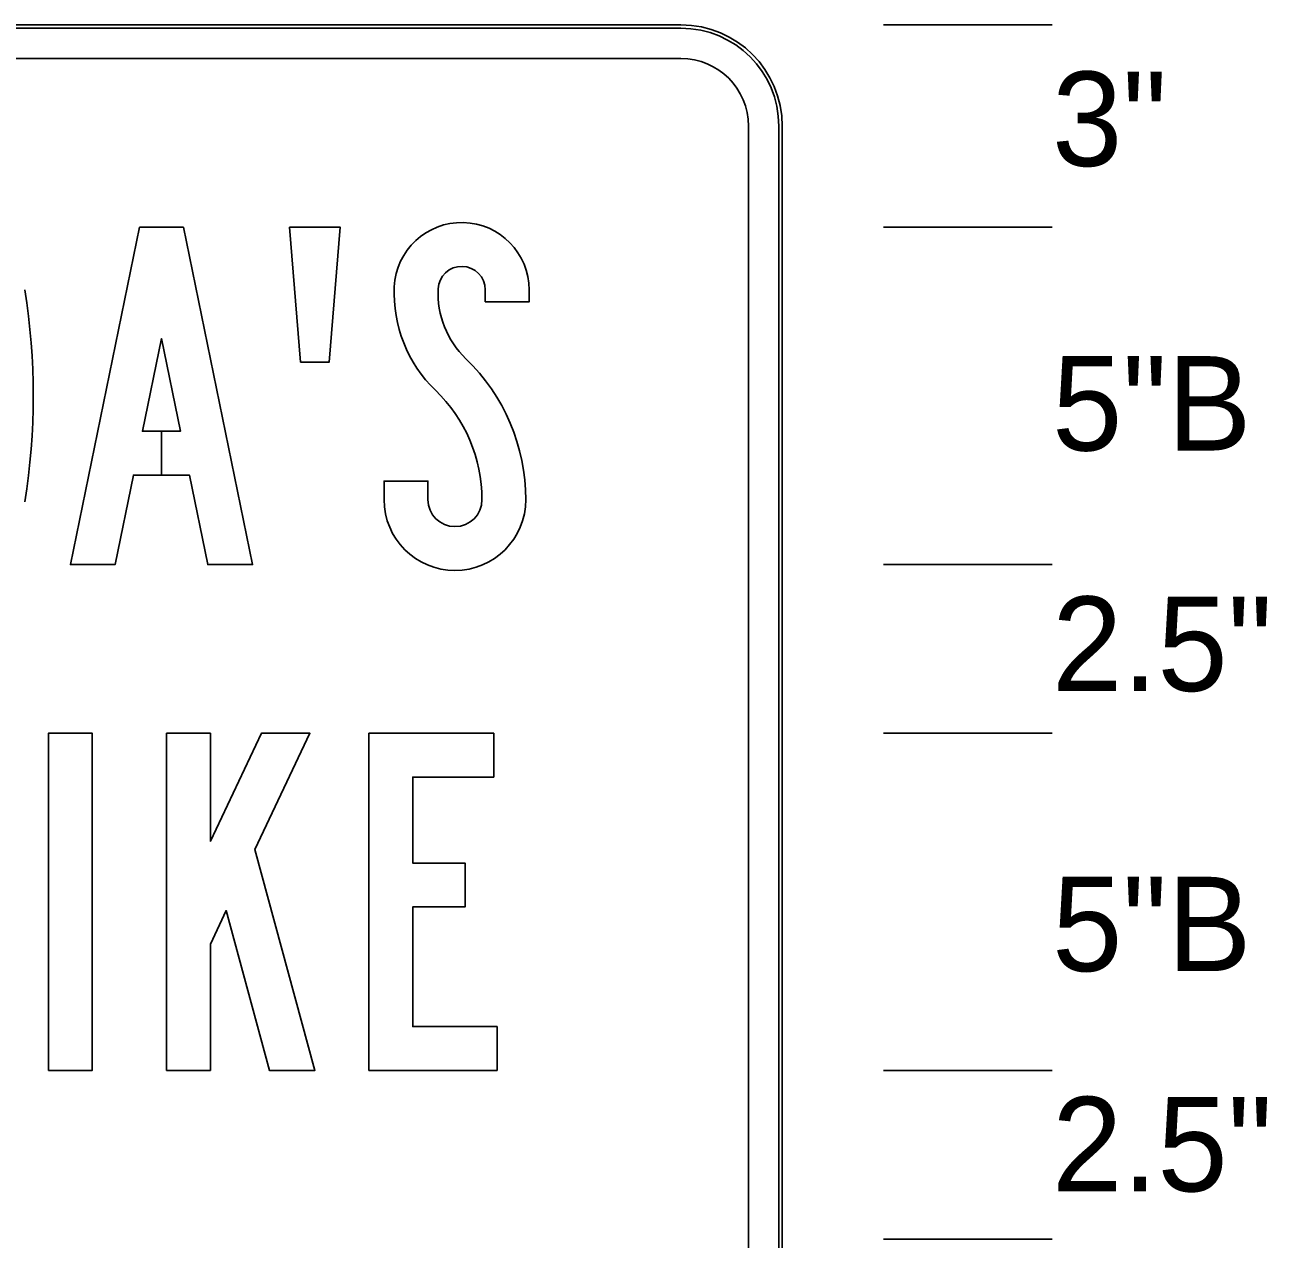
# Model space of a CAD drawing. Extents: x 0 to 770, y 0 to 495.
# Drawn here: x 157.86 to 203.89, y 97.62 to 142.62 of the extents above; entities that cross this region are included whole.
import ezdxf

# ---------------------------------------------------------------- set-up
doc = ezdxf.new("R2010")
doc.units = 0
for name, color, linetype in [('GSBWFill', 7, 'Continuous'), ('GSColorFill', 7, 'Continuous'), ('GSDims', 7, 'Continuous'), ('GSOutline', 7, 'Continuous')]:
    doc.layers.add(name, color=color, linetype=linetype)

msp = doc.modelspace()

# ---------------------------------------------------------------- linework, layer by layer
at = {"layer": 'GSBWFill'}
for p, q in [((182.169, 142.623), (114.669, 142.623)), ((114.669, 141.373), (182.169, 141.373)), ((184.669, 138.873), (184.669, 56.373)), ((185.919, 56.373), (185.919, 138.873))]:
    msp.add_line(p, q, dxfattribs=at)
for points in [[(162.919, 127.56), (163.623, 127.56), (162.919, 130.995), (162.215, 127.56), (162.919, 127.56), (162.919, 125.935), (161.881, 125.935), (161.202, 122.623), (159.544, 122.623), (162.106, 135.123), (163.731, 135.123), (166.294, 122.623), (164.635, 122.623), (163.956, 125.935), (162.919, 125.935)], [(168.075, 130.123), (169.137, 130.123), (169.544, 135.123), (167.669, 135.123)], [(158.731, 103.873), (158.731, 116.373), (160.356, 116.373), (160.356, 103.873)], [(164.731, 103.873), (164.731, 108.56), (165.314, 109.796), (166.922, 103.873), (168.606, 103.873), (166.383, 112.06), (168.419, 116.373), (166.622, 116.373), (164.731, 112.367), (164.731, 116.373), (163.106, 116.373), (163.106, 103.873)], [(175.231, 116.373), (175.231, 114.748), (172.231, 114.748), (172.231, 111.56), (174.169, 111.56), (174.169, 109.935), (172.231, 109.935), (172.231, 105.498), (175.356, 105.498), (175.356, 103.873), (170.606, 103.873), (170.606, 116.373)]]:
    msp.add_lwpolyline(points, close=True, dxfattribs=at)
for points in [[(174.919, 132.798), (174.919, 132.36), (176.544, 132.36), (176.544, 132.798)], [(172.794, 125.029), (172.794, 125.717), (171.169, 125.717), (171.169, 125.029)]]:
    msp.add_lwpolyline(points, dxfattribs=at)
for centre, radius, start, end in [((182.169, 138.873), 3.75, 0, 90), ((182.169, 138.873), 2.5, 0, 90), ((174.044, 132.798), 2.5, 0, 177.3048), ((174.044, 132.798), 0.875, 0, 177.3048), ((176.541, 132.68), 5, 177.3048, 226.0638), ((176.541, 132.68), 3.375, 177.3048, 226.0638), ((169.169, 125.029), 7.25, 0, 46.0638), ((169.169, 125.029), 5.625, 0, 46.0638), ((173.794, 125.029), 2.625, 180, 0), ((173.794, 125.029), 1, 180, 0)]:
    msp.add_arc(centre, radius, start, end, dxfattribs=at)
msp.add_ellipse((133.169, 128.873), major_axis=(0, 25), ratio=0.999988, start_param=4.55443, end_param=4.870348, dxfattribs=at)
at = {"layer": 'GSColorFill'}
for p, q in [((182.169, 142.623), (114.669, 142.623)), ((182.169, 142.623), (114.669, 142.623)), ((182.169, 142.623), (114.669, 142.623)), ((114.669, 142.498), (182.169, 142.498)), ((114.669, 141.373), (182.169, 141.373)), ((184.669, 138.873), (184.669, 56.373)), ((185.794, 138.873), (185.794, 56.373)), ((185.919, 56.373), (185.919, 138.873)), ((185.919, 56.373), (185.919, 138.873)), ((185.919, 56.373), (185.919, 138.873))]:
    msp.add_line(p, q, dxfattribs=at)
for points in [[(162.919, 127.56), (163.623, 127.56), (162.919, 130.995), (162.215, 127.56), (162.919, 127.56), (162.919, 125.935), (161.881, 125.935), (161.202, 122.623), (159.544, 122.623), (162.106, 135.123), (163.731, 135.123), (166.294, 122.623), (164.635, 122.623), (163.956, 125.935), (162.919, 125.935)], [(168.075, 130.123), (169.137, 130.123), (169.544, 135.123), (167.669, 135.123)], [(158.731, 103.873), (158.731, 116.373), (160.356, 116.373), (160.356, 103.873)], [(164.731, 103.873), (164.731, 108.56), (165.314, 109.796), (166.922, 103.873), (168.606, 103.873), (166.383, 112.06), (168.419, 116.373), (166.622, 116.373), (164.731, 112.367), (164.731, 116.373), (163.106, 116.373), (163.106, 103.873)], [(175.231, 116.373), (175.231, 114.748), (172.231, 114.748), (172.231, 111.56), (174.169, 111.56), (174.169, 109.935), (172.231, 109.935), (172.231, 105.498), (175.356, 105.498), (175.356, 103.873), (170.606, 103.873), (170.606, 116.373)]]:
    msp.add_lwpolyline(points, close=True, dxfattribs=at)
for points in [[(174.919, 132.798), (174.919, 132.36), (176.544, 132.36), (176.544, 132.798)], [(172.794, 125.029), (172.794, 125.717), (171.169, 125.717), (171.169, 125.029)]]:
    msp.add_lwpolyline(points, dxfattribs=at)
for centre, radius, start, end in [((182.169, 138.873), 3.75, 0, 90), ((182.169, 138.873), 3.75, 0, 90), ((182.169, 138.873), 3.75, 0, 90), ((182.169, 138.873), 3.625, 0, 90), ((182.169, 138.873), 2.5, 0, 90), ((174.044, 132.798), 2.5, 0, 177.3048), ((174.044, 132.798), 0.875, 0, 177.3048), ((176.541, 132.68), 5, 177.3048, 226.0638), ((176.541, 132.68), 3.375, 177.3048, 226.0638), ((169.169, 125.029), 7.25, 0, 46.0638), ((169.169, 125.029), 5.625, 0, 46.0638), ((173.794, 125.029), 2.625, 180, 0), ((173.794, 125.029), 1, 180, 0)]:
    msp.add_arc(centre, radius, start, end, dxfattribs=at)
msp.add_ellipse((133.169, 128.873), major_axis=(0, 25), ratio=0.999988, start_param=4.55443, end_param=4.870348, dxfattribs=at)
at = {"layer": 'GSDims'}
for p, q in [((189.669, 142.623), (195.919, 142.623)), ((189.669, 135.123), (195.919, 135.123)), ((189.669, 135.123), (195.919, 135.123)), ((189.669, 122.623), (195.919, 122.623)), ((189.669, 122.623), (195.919, 122.623)), ((189.669, 116.373), (195.919, 116.373)), ((189.669, 116.373), (195.919, 116.373)), ((189.669, 103.873), (195.919, 103.873)), ((189.669, 103.873), (195.919, 103.873)), ((189.669, 97.623), (195.919, 97.623))]:
    msp.add_line(p, q, dxfattribs=at)
at = {"layer": 'GSOutline'}
for p, q in [((182.169, 142.623), (114.669, 142.623)), ((182.169, 141.373), (114.669, 141.373)), ((184.669, 56.373), (184.669, 138.873)), ((185.919, 56.373), (185.919, 138.873))]:
    msp.add_line(p, q, dxfattribs=at)
for points in [[(161.202, 122.623), (159.544, 122.623), (162.106, 135.123), (163.731, 135.123), (166.294, 122.623), (164.635, 122.623), (163.956, 125.935), (161.881, 125.935)], [(168.075, 130.123), (169.137, 130.123), (169.544, 135.123), (167.669, 135.123)], [(163.623, 127.56), (162.215, 127.56), (162.919, 130.995)], [(158.731, 103.873), (158.731, 116.373), (160.356, 116.373), (160.356, 103.873)], [(164.731, 103.873), (164.731, 108.56), (165.314, 109.796), (166.922, 103.873), (168.606, 103.873), (166.383, 112.06), (168.419, 116.373), (166.622, 116.373), (164.731, 112.367), (164.731, 116.373), (163.106, 116.373), (163.106, 103.873)], [(175.231, 116.373), (175.231, 114.748), (172.231, 114.748), (172.231, 111.56), (174.169, 111.56), (174.169, 109.935), (172.231, 109.935), (172.231, 105.498), (175.356, 105.498), (175.356, 103.873), (170.606, 103.873), (170.606, 116.373)]]:
    msp.add_lwpolyline(points, close=True, dxfattribs=at)
for points in [[(174.919, 132.798), (174.919, 132.36), (176.544, 132.36), (176.544, 132.798)], [(172.794, 125.029), (172.794, 125.717), (171.169, 125.717), (171.169, 125.029)]]:
    msp.add_lwpolyline(points, dxfattribs=at)
for centre, radius, start, end in [((182.169, 138.873), 3.75, 0, 90), ((182.169, 138.873), 2.5, 0, 90), ((174.044, 132.798), 2.5, 0, 177.3048), ((174.044, 132.798), 0.875, 0, 177.3048), ((176.541, 132.68), 5, 177.3048, 226.0638), ((176.541, 132.68), 3.375, 177.3048, 226.0638), ((169.169, 125.029), 7.25, 0, 46.0638), ((169.169, 125.029), 5.625, 0, 46.0638), ((173.794, 125.029), 2.625, 180, 0), ((173.794, 125.029), 1, 180, 0)]:
    msp.add_arc(centre, radius, start, end, dxfattribs=at)
msp.add_ellipse((133.169, 128.873), major_axis=(0, 25), ratio=0.999988, start_param=4.55443, end_param=4.870348, dxfattribs=at)

# ---------------------------------------------------------------- texts
at = {"layer": 'GSDims'}
for s, p in [('3"', (195.919, 137.39)), ('5"B', (195.919, 126.847)), ('2.5"', (195.919, 117.937)), ('5"B', (195.919, 107.554)), ('2.5"', (195.919, 99.395))]:
    msp.add_text(s, height=3.5, dxfattribs=at).set_placement(p)

doc.saveas('drawing.dxf')
